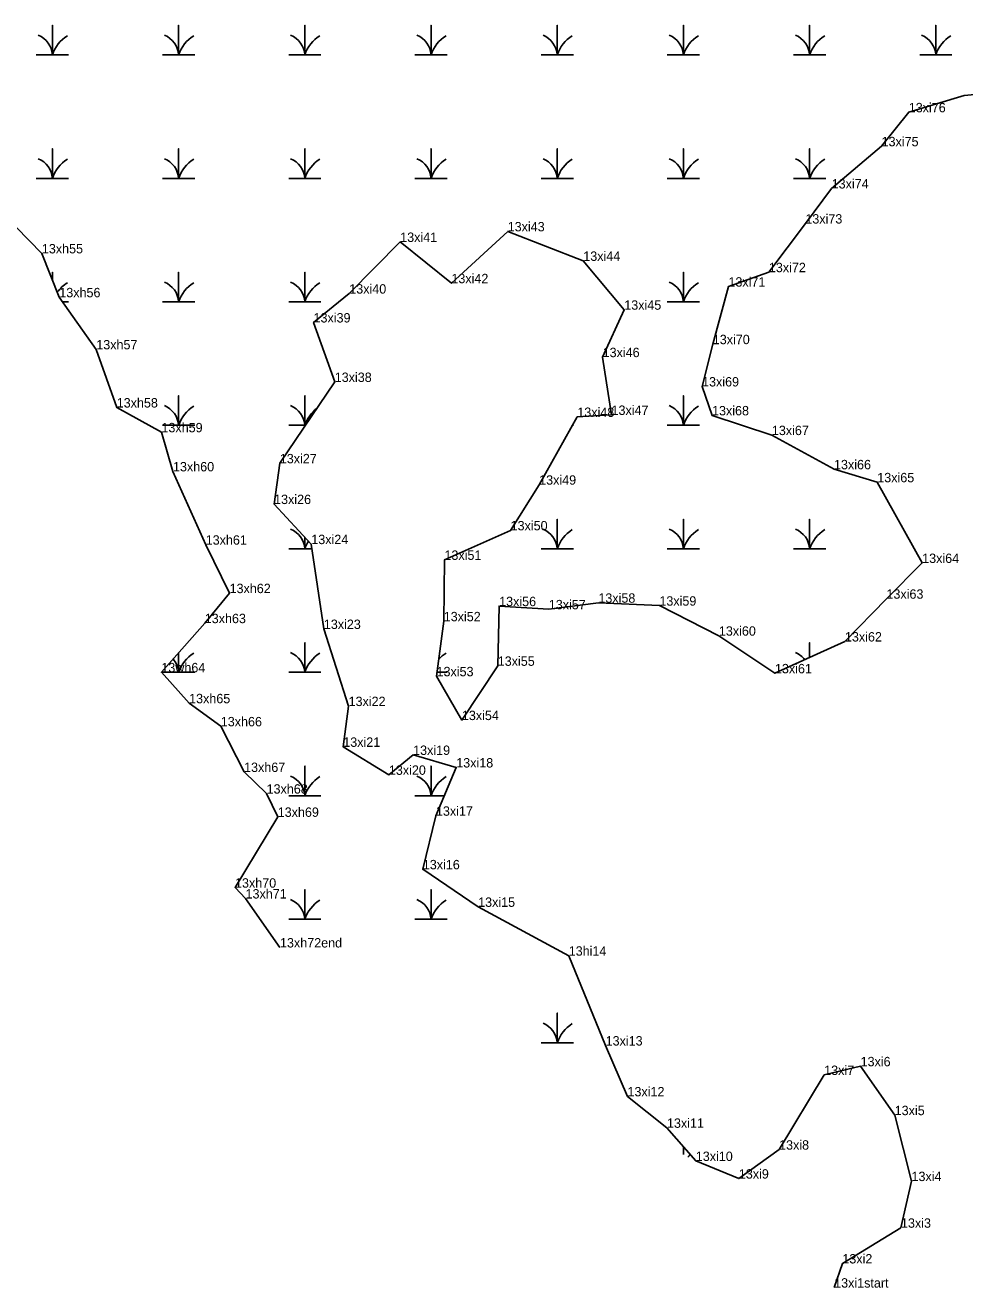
# Model space of a CAD drawing. Extents: x 2072529 to 2268796, y 436423 to 470397.
# Drawn here: x 2248750 to 2249251, y 445549 to 446222 of the extents above; entities that cross this region are included whole.
import ezdxf

# ---------------------------------------------------------------- set-up
doc = ezdxf.new("R2010")
doc.units = 0
for name, color, linetype in [('Exist Environmental Wetland Boundary', 7, 'Continuous'), ('Exist Environmental Wetland Boundary Cogo Comment', 7, 'Continuous'), ('Exist Environmental Wetland Boundary Cogo Point CELL', 7, 'Continuous'), ('Exist Hydro Swamp or Marsh', 7, 'Continuous')]:
    doc.layers.add(name, color=color, linetype=linetype)

msp = doc.modelspace()

# ---------------------------------------------------------------- linework, layer by layer
at = {"layer": 'Exist Environmental Wetland Boundary'}
for points in [[(2248915.29, 446031.48), (2248904, 446063.16), (2248923.03, 446078.56), (2248950.18, 446106.1), (2248977.46, 446084.08), (2249007.46, 446111.72), (2249047.74, 446096), (2249069.58, 446069.96), (2249058.05, 446044.7), (2249062.79, 446013.92), (2249044.57, 446012.84), (2249024.23, 445976.73), (2249009.01, 445952.4), (2248973.75, 445936.68), (2248973.38, 445903.95), (2248969.55, 445874.66), (2248983.05, 445851.3), (2249002.16, 445880.22), (2249002.9, 445912.01), (2249029.36, 445910.33), (2249055.78, 445913.83), (2249088.29, 445912.28), (2249120, 445896.28), (2249149.87, 445876.23), (2249187.17, 445893.17), (2249209.3, 445915.97), (2249228.33, 445935.01), (2249204.4, 445978.02), (2249181.35, 445984.95), (2249148.24, 446003.16), (2249116.35, 446013.68), (2249111.05, 446029.07), (2249116.75, 446051.61), (2249125.09, 446082.27), (2249146.64, 446089.97), (2249166.08, 446115.87), (2249180.1, 446134.56), (2249206.7, 446157.06), (2249221.18, 446175.16), (2249250.77, 446184.17), (2249286.67, 446187.49)], [(2248717.78, 446142.26), (2248759.23, 446099.98), (2248768.52, 446076.6)], [(2248768.52, 446076.6), (2248788.23, 446048.84), (2248799.12, 446017.86), (2248822.95, 446004.65), (2248829.1, 445983.83), (2248846.53, 445944.77), (2248859.26, 445918.96), (2248846.03, 445902.95), (2248822.89, 445876.77), (2248837.69, 445860.28), (2248854.57, 445847.98), (2248866.98, 445823.65), (2248878.98, 445812.11), (2248884.91, 445799.74), (2248862.15, 445762.02), (2248867.77, 445756.23), (2248886.12, 445730.14)], [(2249181.42, 445548.9), (2249185.79, 445561.77), (2249217.04, 445580.8), (2249222.64, 445605.66), (2249213.68, 445640.79), (2249195.52, 445666.83), (2249176.11, 445662.2), (2249152.09, 445622.41), (2249130.64, 445606.99), (2249107.7, 445616.37), (2249092.34, 445634.05), (2249071.29, 445650.81), (2249059.66, 445677.89), (2249039.97, 445725.77), (2248991.71, 445751.79), (2248962.23, 445771.79), (2248969.22, 445800.33), (2248980.04, 445826.04), (2248957.06, 445832.74), (2248944.14, 445822.14), (2248919.83, 445837.05), (2248922.67, 445858.78), (2248909.49, 445899.85), (2248902.79, 445945.07), (2248882.98, 445966.42), (2248886.02, 445988.12), (2248915.29, 446031.48)]]:
    msp.add_lwpolyline(points, dxfattribs=at)
at = {"layer": 'Exist Environmental Wetland Boundary Cogo Point CELL'}
for p, q in [((2249250.77, 446184.17), (2249250.77, 446184.17)), ((2249221.18, 446175.16), (2249221.18, 446175.16)), ((2249206.7, 446157.06), (2249206.7, 446157.06)), ((2249180.1, 446134.56), (2249180.1, 446134.56)), ((2249166.08, 446115.87), (2249166.08, 446115.87)), ((2249007.46, 446111.72), (2249007.46, 446111.72)), ((2248950.18, 446106.1), (2248950.18, 446106.1)), ((2248759.23, 446099.98), (2248759.23, 446099.98)), ((2249047.74, 446096), (2249047.74, 446096)), ((2249146.64, 446089.97), (2249146.64, 446089.97)), ((2248977.46, 446084.08), (2248977.46, 446084.08)), ((2249125.09, 446082.27), (2249125.09, 446082.27)), ((2248768.52, 446076.6), (2248768.52, 446076.6)), ((2248923.03, 446078.56), (2248923.03, 446078.56)), ((2249069.58, 446069.96), (2249069.58, 446069.96)), ((2248904, 446063.16), (2248904, 446063.16)), ((2248788.23, 446048.84), (2248788.23, 446048.84)), ((2249116.75, 446051.61), (2249116.75, 446051.61)), ((2249058.05, 446044.7), (2249058.05, 446044.7)), ((2248915.29, 446031.48), (2248915.29, 446031.48)), ((2249111.05, 446029.07), (2249111.05, 446029.07)), ((2248799.12, 446017.86), (2248799.12, 446017.86)), ((2249044.57, 446012.84), (2249044.57, 446012.84)), ((2249062.79, 446013.92), (2249062.79, 446013.92)), ((2249116.35, 446013.68), (2249116.35, 446013.68)), ((2248822.95, 446004.65), (2248822.95, 446004.65)), ((2249148.24, 446003.16), (2249148.24, 446003.16)), ((2248886.02, 445988.12), (2248886.02, 445988.12)), ((2248829.1, 445983.83), (2248829.1, 445983.83)), ((2249181.35, 445984.95), (2249181.35, 445984.95)), ((2249024.23, 445976.73), (2249024.23, 445976.73)), ((2249204.4, 445978.02), (2249204.4, 445978.02)), ((2248882.98, 445966.42), (2248882.98, 445966.42)), ((2249009.01, 445952.4), (2249009.01, 445952.4)), ((2248846.53, 445944.77), (2248846.53, 445944.77)), ((2248902.79, 445945.07), (2248902.79, 445945.07)), ((2248973.75, 445936.68), (2248973.75, 445936.68)), ((2249228.33, 445935.01), (2249228.33, 445935.01)), ((2248859.26, 445918.96), (2248859.26, 445918.96)), ((2249055.78, 445913.83), (2249055.78, 445913.83)), ((2249209.3, 445915.97), (2249209.3, 445915.97)), ((2249002.9, 445912.01), (2249002.9, 445912.01)), ((2249029.36, 445910.33), (2249029.36, 445910.33)), ((2249088.29, 445912.28), (2249088.29, 445912.28)), ((2248846.03, 445902.95), (2248846.03, 445902.95)), ((2248909.49, 445899.85), (2248909.49, 445899.85)), ((2248973.38, 445903.95), (2248973.38, 445903.95)), ((2249120, 445896.28), (2249120, 445896.28)), ((2249187.17, 445893.17), (2249187.17, 445893.17)), ((2249002.16, 445880.22), (2249002.16, 445880.22)), ((2248822.89, 445876.77), (2248822.89, 445876.77)), ((2248969.55, 445874.66), (2248969.55, 445874.66)), ((2249149.87, 445876.23), (2249149.87, 445876.23)), ((2248837.69, 445860.28), (2248837.69, 445860.28)), ((2248922.67, 445858.78), (2248922.67, 445858.78)), ((2248854.57, 445847.98), (2248854.57, 445847.98)), ((2248983.05, 445851.3), (2248983.05, 445851.3)), ((2248919.83, 445837.05), (2248919.83, 445837.05)), ((2248957.06, 445832.74), (2248957.06, 445832.74)), ((2248980.04, 445826.04), (2248980.04, 445826.04)), ((2248866.98, 445823.65), (2248866.98, 445823.65)), ((2248944.14, 445822.14), (2248944.14, 445822.14)), ((2248878.98, 445812.11), (2248878.98, 445812.11)), ((2248884.91, 445799.74), (2248884.91, 445799.74)), ((2248969.22, 445800.33), (2248969.22, 445800.33)), ((2248962.23, 445771.79), (2248962.23, 445771.79)), ((2248862.15, 445762.02), (2248862.15, 445762.02)), ((2248867.77, 445756.23), (2248867.77, 445756.23)), ((2248991.71, 445751.79), (2248991.71, 445751.79)), ((2248886.12, 445730.14), (2248886.12, 445730.14)), ((2249039.97, 445725.77), (2249039.97, 445725.77)), ((2249059.66, 445677.89), (2249059.66, 445677.89)), ((2249195.52, 445666.83), (2249195.52, 445666.83)), ((2249176.11, 445662.2), (2249176.11, 445662.2)), ((2249071.29, 445650.81), (2249071.29, 445650.81)), ((2249213.68, 445640.79), (2249213.68, 445640.79)), ((2249092.34, 445634.05), (2249092.34, 445634.05)), ((2249152.09, 445622.41), (2249152.09, 445622.41)), ((2249107.7, 445616.37), (2249107.7, 445616.37)), ((2249130.64, 445606.99), (2249130.64, 445606.99)), ((2249222.64, 445605.66), (2249222.64, 445605.66)), ((2249217.04, 445580.8), (2249217.04, 445580.8)), ((2249185.79, 445561.77), (2249185.79, 445561.77)), ((2249181.42, 445548.9), (2249181.42, 445548.9))]:
    msp.add_line(p, q, dxfattribs=at)
at = {"layer": 'Exist Hydro Swamp or Marsh'}
for points in [[(2248756.26, 446205.77), (2248764.86, 446205.77), (2248764.86, 446221.55), (2248764.86, 446205.77), (2248773.47, 446205.77)], [(2248823.51, 446205.77), (2248832.11, 446205.77), (2248832.11, 446221.55), (2248832.11, 446205.77), (2248840.72, 446205.77)], [(2248890.76, 446205.77), (2248899.36, 446205.77), (2248899.36, 446221.55), (2248899.36, 446205.77), (2248907.97, 446205.77)], [(2248958.01, 446205.77), (2248966.61, 446205.77), (2248966.61, 446221.55), (2248966.61, 446205.77), (2248975.22, 446205.77)], [(2249025.26, 446205.77), (2249033.86, 446205.77), (2249033.86, 446221.55), (2249033.86, 446205.77), (2249042.47, 446205.77)], [(2249092.51, 446205.77), (2249101.11, 446205.77), (2249101.11, 446221.55), (2249101.11, 446205.77), (2249109.72, 446205.77)], [(2249159.76, 446205.77), (2249168.36, 446205.77), (2249168.36, 446221.55), (2249168.36, 446205.77), (2249176.97, 446205.77)], [(2249227.01, 446205.77), (2249235.61, 446205.77), (2249235.61, 446221.55), (2249235.61, 446205.77), (2249244.22, 446205.77)], [(2248756.26, 446139.97), (2248764.86, 446139.97), (2248764.86, 446155.75), (2248764.86, 446139.97), (2248773.47, 446139.97)], [(2248823.51, 446139.97), (2248832.11, 446139.97), (2248832.11, 446155.75), (2248832.11, 446139.97), (2248840.72, 446139.97)], [(2248890.76, 446139.97), (2248899.36, 446139.97), (2248899.36, 446155.75), (2248899.36, 446139.97), (2248907.97, 446139.97)], [(2248958.01, 446139.97), (2248966.61, 446139.97), (2248966.61, 446155.75), (2248966.61, 446139.97), (2248975.22, 446139.97)], [(2249025.26, 446139.97), (2249033.86, 446139.97), (2249033.86, 446155.75), (2249033.86, 446139.97), (2249042.47, 446139.97)], [(2249092.51, 446139.97), (2249101.11, 446139.97), (2249101.11, 446155.75), (2249101.11, 446139.97), (2249109.72, 446139.97)], [(2249159.76, 446139.97), (2249168.36, 446139.97), (2249168.36, 446155.75), (2249168.36, 446139.97), (2249176.97, 446139.97)], [(2248764.86, 446085.8), (2248764.86, 446089.95), (2248764.86, 446085.8)], [(2248823.51, 446074.17), (2248832.11, 446074.17), (2248832.11, 446089.95), (2248832.11, 446074.17), (2248840.72, 446074.17)], [(2248890.76, 446074.17), (2248899.36, 446074.17), (2248899.36, 446089.95), (2248899.36, 446074.17), (2248907.97, 446074.17)], [(2249092.51, 446074.17), (2249101.11, 446074.17), (2249101.11, 446089.95), (2249101.11, 446074.17), (2249109.72, 446074.17)], [(2248770.25, 446074.17), (2248773.47, 446074.17)], [(2248823.51, 446008.37), (2248832.11, 446008.37), (2248832.11, 446024.15), (2248832.11, 446008.37), (2248840.72, 446008.37)], [(2248890.76, 446008.37), (2248899.36, 446008.37), (2248899.36, 446024.15), (2248899.36, 446008.37), (2248899.68, 446008.37)], [(2249092.51, 446008.37), (2249101.11, 446008.37), (2249101.11, 446024.15), (2249101.11, 446008.37), (2249109.72, 446008.37)], [(2249042.05, 446008.37), (2249042.47, 446008.37)], [(2249025.26, 445942.57), (2249033.86, 445942.57), (2249033.86, 445958.35), (2249033.86, 445942.57), (2249042.47, 445942.57)], [(2249092.51, 445942.57), (2249101.11, 445942.57), (2249101.11, 445958.35), (2249101.11, 445942.57), (2249109.72, 445942.57)], [(2249159.76, 445942.57), (2249168.36, 445942.57), (2249168.36, 445958.35), (2249168.36, 445942.57), (2249176.97, 445942.57)], [(2248890.76, 445942.57), (2248899.36, 445942.57), (2248899.36, 445948.76)], [(2248899.36, 445948.76), (2248899.36, 445942.57), (2248903.16, 445942.57)], [(2248823.51, 445876.77), (2248832.11, 445876.77), (2248832.11, 445887.21)], [(2248832.11, 445887.21), (2248832.11, 445876.77), (2248840.72, 445876.77)], [(2248890.76, 445876.77), (2248899.36, 445876.77), (2248899.36, 445892.55), (2248899.36, 445876.77), (2248907.97, 445876.77)], [(2249168.36, 445884.63), (2249168.36, 445892.55), (2249168.36, 445884.63)], [(2248969.83, 445876.77), (2248975.22, 445876.77)], [(2248890.76, 445810.97), (2248899.36, 445810.97), (2248899.36, 445826.75), (2248899.36, 445810.97), (2248907.97, 445810.97)], [(2248958.01, 445810.97), (2248966.61, 445810.97), (2248966.61, 445826.75), (2248966.61, 445810.97), (2248973.7, 445810.97)], [(2248890.76, 445745.17), (2248899.36, 445745.17), (2248899.36, 445760.95), (2248899.36, 445745.17), (2248907.97, 445745.17)], [(2248958.01, 445745.17), (2248966.61, 445745.17), (2248966.61, 445760.95), (2248966.61, 445745.17), (2248975.22, 445745.17)], [(2249025.26, 445679.37), (2249033.86, 445679.37), (2249033.86, 445695.15), (2249033.86, 445679.37), (2249042.47, 445679.37)], [(2249101.11, 445619.82), (2249101.11, 445623.95)], [(2249101.11, 445623.95), (2249101.11, 445619.82)]]:
    msp.add_lwpolyline(points, dxfattribs=at)
for centre, radius, start, end in [((2248752.6, 446204.88), 12.3, 4.14034, 67.53497), ((2248783.11, 446199.7), 19.22, 122.12745, 161.62219), ((2248819.85, 446204.88), 12.3, 4.14034, 67.53497), ((2248850.36, 446199.7), 19.22, 122.12745, 161.62219), ((2248887.1, 446204.88), 12.3, 4.14034, 67.53497), ((2248917.61, 446199.7), 19.22, 122.12745, 161.62219), ((2248954.35, 446204.88), 12.3, 4.14034, 67.53497), ((2248984.86, 446199.7), 19.22, 122.12745, 161.62219), ((2249021.6, 446204.88), 12.3, 4.14034, 67.53497), ((2249052.11, 446199.7), 19.22, 122.12745, 161.62219), ((2249088.85, 446204.88), 12.3, 4.14034, 67.53497), ((2249119.36, 446199.7), 19.22, 122.12745, 161.62219), ((2249156.1, 446204.88), 12.3, 4.14034, 67.53497), ((2249186.61, 446199.7), 19.22, 122.12745, 161.62219), ((2249223.35, 446204.88), 12.3, 4.14034, 67.53497), ((2249253.86, 446199.7), 19.22, 122.12745, 161.62219), ((2248752.6, 446139.08), 12.3, 4.14034, 67.53497), ((2248783.11, 446133.9), 19.22, 122.12745, 161.62219), ((2248819.85, 446139.08), 12.3, 4.14034, 67.53497), ((2248850.36, 446133.9), 19.22, 122.12745, 161.62219), ((2248887.1, 446139.08), 12.3, 4.14034, 67.53497), ((2248917.61, 446133.9), 19.22, 122.12745, 161.62219), ((2248954.35, 446139.08), 12.3, 4.14034, 67.53497), ((2248984.86, 446133.9), 19.22, 122.12745, 161.62219), ((2249021.6, 446139.08), 12.3, 4.14034, 67.53497), ((2249052.11, 446133.9), 19.22, 122.12745, 161.62219), ((2249088.85, 446139.08), 12.3, 4.14034, 67.53497), ((2249119.36, 446133.9), 19.22, 122.12745, 161.62219), ((2249156.1, 446139.08), 12.3, 4.14034, 67.53497), ((2249186.61, 446133.9), 19.22, 122.12745, 161.62219), ((2248783.11, 446068.1), 19.22, 122.12745, 144.48343), ((2248819.85, 446073.28), 12.3, 4.14034, 67.53497), ((2248850.36, 446068.1), 19.22, 122.12745, 161.62219), ((2248887.1, 446073.28), 12.3, 4.14034, 67.53497), ((2248917.61, 446068.1), 19.22, 122.12745, 161.62219), ((2249088.85, 446073.28), 12.3, 4.14034, 67.53497), ((2249119.36, 446068.1), 19.22, 122.12745, 161.62219), ((2248819.85, 446007.48), 12.3, 4.14034, 67.53497), ((2248850.36, 446002.3), 19.22, 122.12745, 161.62219), ((2248887.1, 446007.48), 12.3, 4.14034, 67.53497), ((2248917.61, 446002.3), 19.22, 127.63338, 161.62219), ((2249088.85, 446007.48), 12.3, 4.14034, 67.53497), ((2249119.36, 446002.3), 19.22, 122.12745, 161.62219), ((2248887.1, 445941.68), 12.3, 4.14034, 67.53497), ((2248917.61, 445936.5), 19.22, 148.04924, 161.62219), ((2249021.6, 445941.68), 12.3, 4.14034, 67.53497), ((2249052.11, 445936.5), 19.22, 122.12745, 161.62219), ((2249088.85, 445941.68), 12.3, 4.14034, 67.53497), ((2249119.36, 445936.5), 19.22, 122.12745, 161.62219), ((2249156.1, 445941.68), 12.3, 4.14034, 67.53497), ((2249186.61, 445936.5), 19.22, 122.12745, 161.62219), ((2248850.36, 445870.7), 19.22, 122.12745, 161.62219), ((2248887.1, 445875.88), 12.3, 4.14034, 67.53497), ((2248917.61, 445870.7), 19.22, 122.12745, 161.62219), ((2248984.86, 445870.7), 19.22, 122.12745, 137.25738), ((2249156.1, 445875.88), 12.3, 38.051, 67.53497), ((2248819.85, 445875.88), 12.3, 4.14034, 40.65463), ((2248887.1, 445810.08), 12.3, 4.14034, 67.53497), ((2248917.61, 445804.9), 19.22, 122.12745, 161.62219), ((2248954.35, 445810.08), 12.3, 4.14034, 67.53497), ((2248984.86, 445804.9), 19.22, 122.12745, 161.62219), ((2248887.1, 445744.28), 12.3, 4.14034, 67.53497), ((2248917.61, 445739.1), 19.22, 122.12745, 161.62219), ((2248954.35, 445744.28), 12.3, 4.14034, 67.53497), ((2248984.86, 445739.1), 19.22, 122.12745, 161.62219), ((2249021.6, 445678.48), 12.3, 4.14034, 67.53497), ((2249052.11, 445673.3), 19.22, 122.12745, 161.62219), ((2249119.36, 445607.5), 19.22, 139.92518, 145.41126)]:
    msp.add_arc(centre, radius, start, end, dxfattribs=at)

# ---------------------------------------------------------------- texts
at = {"layer": 'Exist Environmental Wetland Boundary Cogo Comment'}
for s, p in [('13xi76', (2249221.18, 446175.16)), ('13xi75', (2249206.7, 446157.06)), ('13xi74', (2249180.1, 446134.56)), ('13xi43', (2249007.46, 446111.72)), ('13xi73', (2249166.08, 446115.87)), ('13xi41', (2248950.18, 446106.1)), ('13xh55', (2248759.23, 446099.98)), ('13xi44', (2249047.74, 446096)), ('13xi72', (2249146.64, 446089.97)), ('13xi42', (2248977.46, 446084.08)), ('13xh56', (2248768.52, 446076.6)), ('13xi40', (2248923.03, 446078.56)), ('13xi71', (2249125.09, 446082.27)), ('13xi45', (2249069.58, 446069.96)), ('13xi39', (2248904, 446063.16)), ('13xi70', (2249116.75, 446051.61)), ('13xh57', (2248788.23, 446048.84)), ('13xi46', (2249058.05, 446044.7)), ('13xi38', (2248915.29, 446031.48)), ('13xi69', (2249111.05, 446029.07)), ('13xh58', (2248799.12, 446017.86)), ('13xi48', (2249044.57, 446012.84)), ('13xi47', (2249062.79, 446013.92)), ('13xi68', (2249116.35, 446013.68)), ('13xh59', (2248822.95, 446004.65)), ('13xi67', (2249148.24, 446003.16)), ('13xh60', (2248829.1, 445983.83)), ('13xi27', (2248886.02, 445988.12)), ('13xi66', (2249181.35, 445984.95)), ('13xi49', (2249024.23, 445976.73)), ('13xi65', (2249204.4, 445978.02)), ('13xi26', (2248882.98, 445966.42)), ('13xi50', (2249009.01, 445952.4)), ('13xh61', (2248846.53, 445944.77)), ('13xi24', (2248902.79, 445945.07)), ('13xi51', (2248973.75, 445936.68)), ('13xi64', (2249228.33, 445935.01)), ('13xh62', (2248859.26, 445918.96)), ('13xi63', (2249209.3, 445915.97)), ('13xi56', (2249002.9, 445912.01)), ('13xi57', (2249029.36, 445910.33)), ('13xi58', (2249055.78, 445913.83)), ('13xi59', (2249088.29, 445912.28)), ('13xh63', (2248846.03, 445902.95)), ('13xi52', (2248973.38, 445903.95)), ('13xi23', (2248909.49, 445899.85)), ('13xi60', (2249120, 445896.28)), ('13xi62', (2249187.17, 445893.17)), ('13wh64', (2248822.89, 445876.77)), ('13xi53', (2248969.55, 445874.66)), ('13xi55', (2249002.16, 445880.22)), ('13xi61', (2249149.87, 445876.23)), ('13xh65', (2248837.69, 445860.28)), ('13xi22', (2248922.67, 445858.78)), ('13xh66', (2248854.57, 445847.98)), ('13xi54', (2248983.05, 445851.3)), ('13xi21', (2248919.83, 445837.05)), ('13xi19', (2248957.06, 445832.74)), ('13xh67', (2248866.98, 445823.65)), ('13xi20', (2248944.14, 445822.14)), ('13xi18', (2248980.04, 445826.04)), ('13xh68', (2248878.98, 445812.11)), ('13xi17', (2248969.22, 445800.33)), ('13xh69', (2248884.91, 445799.74)), ('13xi16', (2248962.23, 445771.79)), ('13xh70', (2248862.15, 445762.02)), ('13xh71', (2248867.77, 445756.23)), ('13xi15', (2248991.71, 445751.79)), ('13xh72end', (2248886.12, 445730.14)), ('13hi14', (2249039.97, 445725.77)), ('13xi13', (2249059.66, 445677.89)), ('13xi6', (2249195.52, 445666.83)), ('13xi7', (2249176.11, 445662.2)), ('13xi12', (2249071.29, 445650.81)), ('13xi5', (2249213.68, 445640.79)), ('13xi11', (2249092.34, 445634.05)), ('13xi8', (2249152.09, 445622.41)), ('13xi10', (2249107.7, 445616.37)), ('13xi9', (2249130.64, 445606.99)), ('13xi4', (2249222.64, 445605.66)), ('13xi3', (2249217.04, 445580.8)), ('13xi2', (2249185.79, 445561.77)), ('13xi1start', (2249181.42, 445548.9))]:
    msp.add_text(s, height=5, dxfattribs=at).set_placement(p)

doc.saveas('drawing.dxf')
